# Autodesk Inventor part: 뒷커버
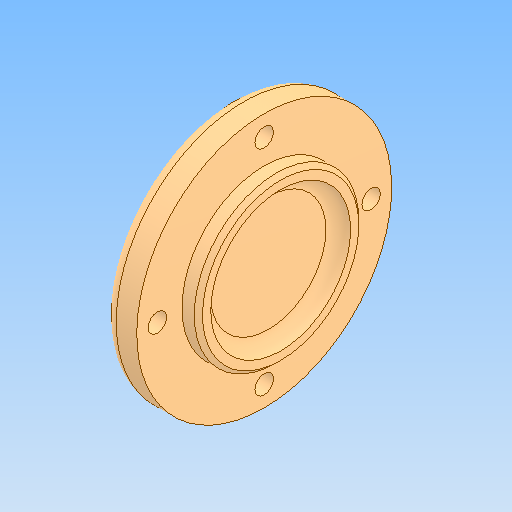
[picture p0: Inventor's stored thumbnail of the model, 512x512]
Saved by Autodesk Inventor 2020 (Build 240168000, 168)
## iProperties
Created: 2024-09
Part Number: 뒷커버
Material: 알루미늄 6061
Document SubType Name: Modeling
Designer: oem
Density: 2.7 g/cm^3
Appearance: 기본값
Author: jhkim
Sending System: Autodesk Inventor 2025
Preprocessor: ST-DEVELOPER v20
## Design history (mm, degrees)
feature "솔리드1"
node "솔리드2"
